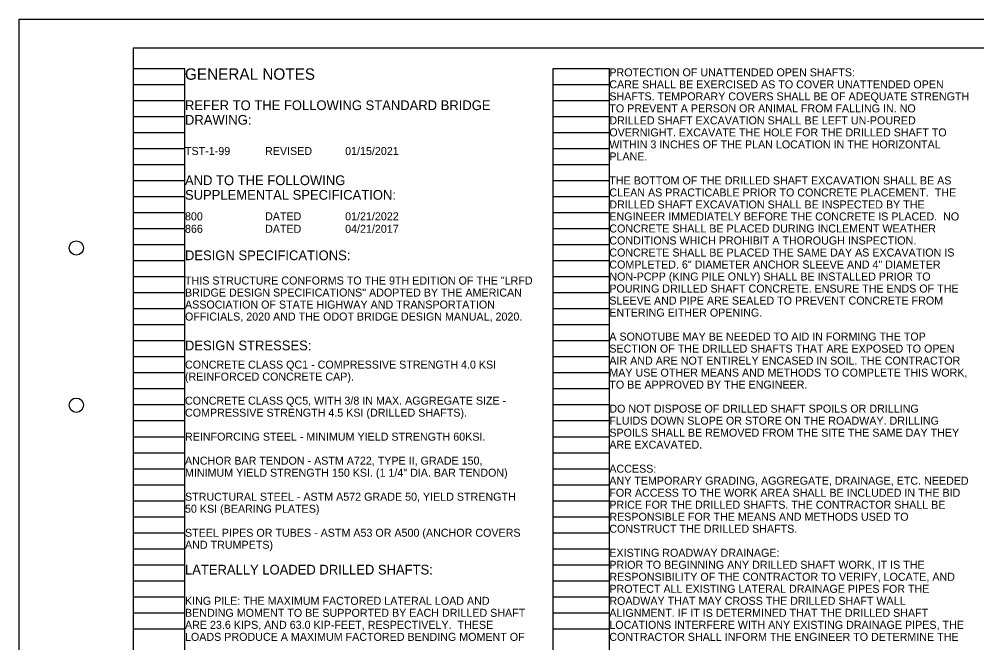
# Model space of a CAD drawing. Extents: x -0.2 to 33.8, y -0.1 to 21.9.
# Drawn here: x -0.22 to 16.52, y 10.96 to 21.87 of the extents above; entities that cross this region are included whole.
import ezdxf

# ---------------------------------------------------------------- set-up
doc = ezdxf.new("R2010")
doc.units = 0
for name, color, linetype in [('SH_Border', 7, 'Continuous'), ('SH_Cut_Line', 7, 'Continuous'), ('SH_Data', 7, 'Continuous'), ('SH_Text', 7, 'Continuous')]:
    doc.layers.add(name, color=color, linetype=linetype)

msp = doc.modelspace()

# ---------------------------------------------------------------- linework, layer by layer
at = {"layer": 'SH_Border'}
msp.add_lwpolyline([(1.775, 21.368), (33.275, 21.368), (33.275, 0.368), (1.775, 0.368)], close=True, dxfattribs=at)
for centre in [(0.775, 17.868), (0.775, 15.118)]:
    msp.add_circle(centre, 0.125, dxfattribs=at)
at = {"layer": 'SH_Cut_Line'}
msp.add_lwpolyline([(-0.225, 21.868), (33.775, 21.868), (33.775, -0.132), (-0.225, -0.132)], close=True, dxfattribs=at)
at = {"layer": 'SH_Data'}
for p, q in [((1.775, 0.848), (1.775, 21.008)), ((1.775, 21.008), (2.675, 21.008)), ((2.675, 0.848), (2.675, 21.008)), ((9.115, 0.848), (9.115, 21.008)), ((9.115, 21.008), (10.095, 21.008)), ((10.095, 0.848), (10.095, 21.008)), ((1.775, 20.728), (2.675, 20.728)), ((9.115, 20.728), (10.095, 20.728)), ((1.775, 20.448), (2.675, 20.448)), ((9.115, 20.448), (10.095, 20.448)), ((1.775, 20.168), (2.675, 20.168)), ((9.115, 20.168), (10.095, 20.168)), ((1.775, 19.888), (2.675, 19.888)), ((9.115, 19.888), (10.095, 19.888)), ((1.775, 19.608), (2.675, 19.608)), ((9.115, 19.608), (10.095, 19.608)), ((1.775, 19.328), (2.675, 19.328)), ((9.115, 19.328), (10.095, 19.328)), ((1.775, 19.048), (2.675, 19.048)), ((9.115, 19.048), (10.095, 19.048)), ((1.775, 18.768), (2.675, 18.768)), ((9.115, 18.768), (10.095, 18.768)), ((1.775, 18.488), (2.675, 18.488)), ((9.115, 18.488), (10.095, 18.488)), ((1.775, 18.208), (2.675, 18.208)), ((9.115, 18.208), (10.095, 18.208)), ((1.775, 17.928), (2.675, 17.928)), ((9.115, 17.928), (10.095, 17.928)), ((1.775, 17.648), (2.675, 17.648)), ((9.115, 17.648), (10.095, 17.648)), ((1.775, 17.368), (2.675, 17.368)), ((9.115, 17.368), (10.095, 17.368)), ((1.775, 17.088), (2.675, 17.088)), ((9.115, 17.088), (10.095, 17.088)), ((1.775, 16.808), (2.675, 16.808)), ((9.115, 16.808), (10.095, 16.808)), ((1.775, 16.528), (2.675, 16.528)), ((9.115, 16.528), (10.095, 16.528)), ((1.775, 16.248), (2.675, 16.248)), ((9.115, 16.248), (10.095, 16.248)), ((1.775, 15.968), (2.675, 15.968)), ((9.115, 15.968), (10.095, 15.968)), ((1.775, 15.688), (2.675, 15.688)), ((9.115, 15.688), (10.095, 15.688)), ((1.775, 15.408), (2.675, 15.408)), ((9.115, 15.408), (10.095, 15.408)), ((1.775, 15.128), (2.675, 15.128)), ((9.115, 15.128), (10.095, 15.128)), ((1.775, 14.848), (2.675, 14.848)), ((9.115, 14.848), (10.095, 14.848)), ((1.775, 14.568), (2.675, 14.568)), ((9.115, 14.568), (10.095, 14.568)), ((1.775, 14.288), (2.675, 14.288)), ((9.115, 14.288), (10.095, 14.288)), ((1.775, 14.008), (2.675, 14.008)), ((9.115, 14.008), (10.095, 14.008)), ((1.775, 13.728), (2.675, 13.728)), ((9.115, 13.728), (10.095, 13.728)), ((1.775, 13.448), (2.675, 13.448)), ((9.115, 13.448), (10.095, 13.448)), ((1.775, 13.168), (2.675, 13.168)), ((9.115, 13.168), (10.095, 13.168)), ((1.775, 12.888), (2.675, 12.888)), ((9.115, 12.888), (10.095, 12.888)), ((1.775, 12.608), (2.675, 12.608)), ((9.115, 12.608), (10.095, 12.608)), ((1.775, 12.328), (2.675, 12.328)), ((9.115, 12.328), (10.095, 12.328)), ((1.775, 12.048), (2.675, 12.048)), ((9.115, 12.048), (10.095, 12.048)), ((1.775, 11.768), (2.675, 11.768)), ((9.115, 11.768), (10.095, 11.768)), ((1.775, 11.488), (2.675, 11.488)), ((9.115, 11.488), (10.095, 11.488)), ((1.775, 11.208), (2.675, 11.208)), ((9.115, 11.208), (10.095, 11.208))]:
    msp.add_line(p, q, dxfattribs=at)

# ---------------------------------------------------------------- texts
for s, height, p in [('GENERAL NOTES', 0.2, (2.675, 20.808)), ('PROTECTION OF UNATTENDED OPEN SHAFTS:', 0.14, (10.095, 20.868)), ('CARE SHALL BE EXERCISED AS TO COVER UNATTENDED OPEN ', 0.14, (10.095, 20.658)), ('REFER TO THE FOLLOWING STANDARD BRIDGE', 0.17, (2.675, 20.278)), ('SHAFTS. TEMPORARY COVERS SHALL BE OF ADEQUATE STRENGTH ', 0.14, (10.095, 20.448)), ('TO PREVENT A PERSON OR ANIMAL FROM FALLING IN. NO ', 0.14, (10.095, 20.238)), ('DRAWING:', 0.17, (2.675, 20.023)), ('DRILLED SHAFT EXCAVATION SHALL BE LEFT UN-POURED ', 0.14, (10.095, 20.028)), ('OVERNIGHT. EXCAVATE THE HOLE FOR THE DRILLED SHAFT TO ', 0.14, (10.095, 19.818)), ('TST-1-99', 0.14, (2.675, 19.493)), ('REVISED', 0.14, (4.075, 19.493)), ('01/15/2021', 0.14, (5.475, 19.493)), ('WITHIN 3 INCHES OF THE PLAN LOCATION IN THE HORIZONTAL ', 0.14, (10.095, 19.608)), ('PLANE. ', 0.14, (10.095, 19.398)), ('AND TO THE FOLLOWING', 0.17, (2.675, 18.966)), ('THE BOTTOM OF THE DRILLED SHAFT EXCAVATION SHALL BE AS ', 0.14, (10.095, 18.978)), ('SUPPLEMENTAL SPECIFICATION:', 0.17, (2.675, 18.711)), ('CLEAN AS PRACTICABLE PRIOR TO CONCRETE PLACEMENT.  THE ', 0.14, (10.095, 18.768)), ('DRILLED SHAFT EXCAVATION SHALL BE INSPECTED BY THE ', 0.14, (10.095, 18.558)), ('ENGINEER IMMEDIATELY BEFORE THE CONCRETE IS PLACED.  NO ', 0.14, (10.095, 18.348)), ('CONCRETE SHALL BE PLACED DURING INCLEMENT WEATHER ', 0.14, (10.095, 18.138)), ('CONDITIONS WHICH PROHIBIT A THOROUGH INSPECTION.  ', 0.14, (10.095, 17.928)), ('DESIGN SPECIFICATIONS:', 0.17, (2.675, 17.654)), ('CONCRETE SHALL BE PLACED THE SAME DAY AS EXCAVATION IS ', 0.14, (10.095, 17.718)), ('COMPLETED. 6" DIAMETER ANCHOR SLEEVE AND 4" DIAMETER ', 0.14, (10.095, 17.508)), ('NON-PCPP (KING PILE ONLY) SHALL BE INSTALLED PRIOR TO ', 0.14, (10.095, 17.298)), ('THIS STRUCTURE CONFORMS TO THE 9TH EDITION OF THE "LRFD ', 0.14, (2.675, 17.228)), ('BRIDGE DESIGN SPECIFICATIONS" ADOPTED BY THE AMERICAN ', 0.14, (2.675, 17.018)), ('POURING DRILLED SHAFT CONCRETE. ENSURE THE ENDS OF THE ', 0.14, (10.095, 17.088)), ('ASSOCIATION OF STATE HIGHWAY AND TRANSPORTATION ', 0.14, (2.675, 16.808)), ('SLEEVE AND PIPE ARE SEALED TO PREVENT CONCRETE FROM ', 0.14, (10.095, 16.878)), ('ENTERING EITHER OPENING.', 0.14, (10.095, 16.668)), ('OFFICIALS, 2020 AND THE ODOT BRIDGE DESIGN MANUAL, 2020.', 0.14, (2.675, 16.598)), ('DESIGN STRESSES:', 0.17, (2.675, 16.078)), ('A SONOTUBE MAY BE NEEDED TO AID IN FORMING THE TOP ', 0.14, (10.095, 16.248)), ('SECTION OF THE DRILLED SHAFTS THAT ARE EXPOSED TO OPEN ', 0.14, (10.095, 16.038)), ('AIR AND ARE NOT ENTIRELY ENCASED IN SOIL. THE CONTRACTOR ', 0.14, (10.095, 15.828)), ('CONCRETE CLASS QC1 - COMPRESSIVE STRENGTH 4.0 KSI', 0.14, (2.675, 15.758)), ('MAY USE OTHER MEANS AND METHODS TO COMPLETE THIS WORK, ', 0.14, (10.095, 15.618)), ('(REINFORCED CONCRETE CAP).', 0.14, (2.675, 15.548)), ('TO BE APPROVED BY THE ENGINEER.', 0.14, (10.095, 15.408)), ('CONCRETE CLASS QC5, WITH 3/8 IN MAX. AGGREGATE SIZE -', 0.14, (2.675, 15.128)), ('DO NOT DISPOSE OF DRILLED SHAFT SPOILS OR DRILLING ', 0.14, (10.095, 14.988)), ('COMPRESSIVE STRENGTH 4.5 KSI (DRILLED SHAFTS).', 0.14, (2.675, 14.918)), ('FLUIDS DOWN SLOPE OR STORE ON THE ROADWAY. DRILLING ', 0.14, (10.095, 14.778)), ('REINFORCING STEEL - MINIMUM YIELD STRENGTH 60KSI.', 0.14, (2.675, 14.498)), ('SPOILS SHALL BE REMOVED FROM THE SITE THE SAME DAY THEY ', 0.14, (10.095, 14.568)), ('ARE EXCAVATED.', 0.14, (10.095, 14.358)), ('ANCHOR BAR TENDON - ASTM A722, TYPE II, GRADE 150, ', 0.14, (2.675, 14.078)), ('ACCESS:', 0.14, (10.095, 13.938)), ('MINIMUM YIELD STRENGTH 150 KSI. (1 1/4" DIA. BAR TENDON)', 0.14, (2.675, 13.868)), ('ANY TEMPORARY GRADING, AGGREGATE, DRAINAGE, ETC. NEEDED ', 0.14, (10.095, 13.728)), ('STRUCTURAL STEEL - ASTM A572 GRADE 50, YIELD STRENGTH ', 0.14, (2.675, 13.448)), ('FOR ACCESS TO THE WORK AREA SHALL BE INCLUDED IN THE BID ', 0.14, (10.095, 13.518)), ('PRICE FOR THE DRILLED SHAFTS. THE CONTRACTOR SHALL BE ', 0.14, (10.095, 13.308)), ('50 KSI (BEARING PLATES)', 0.14, (2.675, 13.238)), ('RESPONSIBLE FOR THE MEANS AND METHODS USED TO ', 0.14, (10.095, 13.098)), ('STEEL PIPES OR TUBES - ASTM A53 OR A500 (ANCHOR COVERS ', 0.14, (2.675, 12.818)), ('CONSTRUCT THE DRILLED SHAFTS.', 0.14, (10.095, 12.888)), ('AND TRUMPETS)', 0.14, (2.675, 12.608)), ('EXISTING ROADWAY DRAINAGE:', 0.14, (10.095, 12.468)), ('PRIOR TO BEGINNING ANY DRILLED SHAFT WORK, IT IS THE ', 0.14, (10.095, 12.258)), ('LATERALLY LOADED DRILLED SHAFTS:', 0.17, (2.675, 12.158)), ('RESPONSIBILITY OF THE CONTRACTOR TO VERIFY, LOCATE, AND ', 0.14, (10.095, 12.048)), ('PROTECT ALL EXISTING LATERAL DRAINAGE PIPES FOR THE ', 0.14, (10.095, 11.838)), ('KING PILE: THE MAXIMUM FACTORED LATERAL LOAD AND ', 0.14, (2.675, 11.628)), ('ROADWAY THAT MAY CROSS THE DRILLED SHAFT WALL ', 0.14, (10.095, 11.628)), ('BENDING MOMENT TO BE SUPPORTED BY EACH DRILLED SHAFT ', 0.14, (2.675, 11.418)), ('ALIGNMENT. IF IT IS DETERMINED THAT THE DRILLED SHAFT ', 0.14, (10.095, 11.418)), ('ARE 23.6 KIPS, AND 63.0 KIP-FEET, RESPECTIVELY.  THESE ', 0.14, (2.675, 11.208)), ('LOCATIONS INTERFERE WITH ANY EXISTING DRAINAGE PIPES, THE ', 0.14, (10.095, 11.208)), ('LOADS PRODUCE A MAXIMUM FACTORED BENDING MOMENT OF ', 0.14, (2.675, 10.998)), ('CONTRACTOR SHALL INFORM THE ENGINEER TO DETERMINE THE ', 0.14, (10.095, 10.998))]:
    msp.add_text(s, height=height, dxfattribs=at).set_placement(p)
at = {"layer": 'SH_Text'}
for s, p in [('800', (2.675, 18.351)), ('DATED', (4.075, 18.351)), ('01/21/2022', (5.475, 18.351)), ('866', (2.675, 18.132)), ('DATED', (4.075, 18.132)), ('04/21/2017', (5.475, 18.132))]:
    msp.add_text(s, height=0.14, dxfattribs=at).set_placement(p)

doc.saveas('drawing.dxf')
